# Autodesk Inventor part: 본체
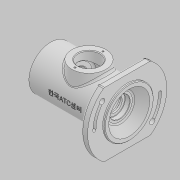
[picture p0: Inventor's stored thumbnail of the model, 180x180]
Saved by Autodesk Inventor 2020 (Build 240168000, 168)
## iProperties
Created: 2022-05
Part Number: 본체
Material: 일반
Document SubType Name: Modeling
Designer: User
Density: 1 g/cm^3
Appearance: 기본값
Author: User
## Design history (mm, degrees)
sketch "스케치1"
  geometry: L1 (0, 0)-(115, 0); L2 (115, 0)-(115, 36); L3 (115, 36)-(112, 36); L4 (112, 36)-(112, 58); L5 (112, 58)-(102, 58); L6 (102, 58)-(102, 32); L7 (102, 32)-(0, 32); L8 (0, 32)-(0, 0); L9 (11, 22.5)-(22, 22.5); L10 (22, 22.5)-(22, 17.5); L11 (22, 17.5)-(23.75, 17.5); L12 (23.75, 17.5)-(23.75, 18.5); L13 (23.75, 18.5)-(26, 18.5); L14 (26, 18.5)-(26, 17.5); L15 (26, 17.5)-(37, 17.5); L16 (37, 17.5)-(37, 27); L17 (75, 27)-(75, 17.5); L18 (75, 17.5)-(86, 17.5); L19 (86, 17.5)-(86, 15); L20 (86, 15)-(91, 15); L21 (91, 15)-(91, 11); L22 (91, 11)-(93.7, 11); L23 (93.7, 11)-(93.7, 15); L24 (101, 20)-(115, 30); L25 (93.7, 15)-(101, 15); L26 (101, 15)-(101, 20); L27 (37, 27)-(75, 27); L28 (11, 22.5)-(11, 24); L29 (11, 24)-(8, 24); L30 (8, 24)-(8, 22.5); L31 (8, 22.5)-(0, 22.5)
  constraints: 62 end point, 21 perpendicular, 4 horizontal, 2 point on line, 1 parallel, 1 vertical
  dimensions: "d0" = 115 distance of L1.start L1.end; "d1" = 72 diameter of L3 L1; "d2" = 116 diameter of L5 L1; "d3" = 64 diameter of L7 L1; "d4" = 13 distance between parallel lines of L6 L2; "d5" = 3 distance of L2.end L3.end; "d6" = 60 diameter of L24.end L1; "d7" = 40 diameter of L24.start L1; "d8" = 14 horizontal distance of L24.end L24.start; "d9" = 30 diameter of L25 L1; "d10" = 22 diameter of L22 L1; "d11" = 30 diameter of L20 L1; "d12" = 35 diameter of L18 L1; "d13" = 54 diameter of L27 L1; "d14" = 35 diameter of L15 L1; "d15" = 37 diameter of L13 L1; "d16" = 35 diameter of L11 L1; "d17" = 45 diameter of L9 L1; "d18" = 48 diameter of L29 L1; "d19" = 45 diameter of L31 L1; "d20" = 8 distance of L30.end L31.end; "d21" = 22 distance between parallel lines of L10 L8; "d22" = 3 distance of L28.end L29.end; "d23" = 29 distance between parallel lines of L19 L2; "d24" = 5 distance of L19.end L20.end; "d25" = 11 distance of L17.end L18.end; "d26" = 38 distance of L16.end L17.start; "d27" = 11 distance of L14.end L15.end; "d28" = 1.75 distance of L10.end L11.end; "d29" = 7.3 distance of L23.end L25.end
revolve "회전1" sketch "스케치1" stored, may be unused: angle "d30" = 90 deg
sketch "스케치2"
  geometry: L1 (-58, 47)-(58, 47); L2 (58, 47)-(58, -47); L3 (58, -47)-(-58, -47); L4 (-58, -47)-(-58, 47); A1 r 58 centre (0, 0) between (-58, 0) and (58, 0) reference; 5 further points
  constraints: 8 end point, 2 midpoint, 2 parallel, 2 point on circle, 1 horizontal, 1 horizontal alignment, 1 perpendicular
  dimensions: "d31" = 94 distance of L1.end L2.end
extrude "돌출1" cut sketch "스케치2" extent not by distance; stored distance "d32" = 0; taper "d33" = 0 deg
node "작업 평면1"
sketch "스케치3"
  geometry: C1 r 25 at (-56, 0); 1 further point
  constraints: 1 centre point, 1 horizontal alignment
  dimensions: "d35" = 50 diameter of C1; "d36" = 56 distance of C1.centre point (0, 0)
extrude "돌출2" join sketch "스케치3" stored distance "d37" = 10; taper "d38" = 5 deg
sketch "스케치4"
  geometry: C1 r 25 at (0, 0) reference; 2 further points
  constraints: 1 coincident
hole "구멍1" sketch "스케치4" at (0, 0) diameter "d39" = 32; stored, may be unused: countersink angle "d43" = 90 deg, drill point angle "d45" = 118 deg; dims "d40" = 6, "d41" = 4, "d42" = 2, "d44" = 8
sketch "스케치5"
  geometry: L1 (-48, 0)-(48, 0); L2 (-36.77, -30.854)-(36.77, 30.854); A1 r 48 centre (0, 0) between (48, 0) and (36.77, 30.854); A2 r 48 centre (0, 0) between (48, 0) and (36.77, 30.854); A3 r 52 centre (0, 0) between (52, 0) and (39.834, 33.425); A4 r 44 centre (0, 0) between (44, 0) and (33.706, 28.283); A5 r 4 centre (48, 0) between (44, 0) and (52, 0); A6 r 4 centre (36.77, 30.854) between (39.834, 33.425) and (33.706, 28.283); A7 r 50.25 centre (0, 0) between (50.25, 0) and (38.494, 32.3); A8 r 2.25 centre (48, 0) between (45.75, 0) and (50.25, 0); A9 r 45.75 centre (0, 0) between (45.75, 0) and (35.047, 29.408); A10 r 2.25 centre (36.77, 30.854) between (38.494, 32.3) and (35.047, 29.408); A11 r 48 centre (0, 0) between (-48, 0) and (-36.77, -30.854); A12 r 52 centre (0, 0) between (-52, 0) and (-39.834, -33.425); A13 r 44 centre (0, 0) between (-44, 0) and (-33.706, -28.283); A14 r 4 centre (-48, 0) between (-44, 0) and (-52, 0); A15 r 4 centre (-36.77, -30.854) between (-39.834, -33.425) and (-33.706, -28.283); A16 r 45.75 centre (0, 0) between (-45.75, 0) and (-35.047, -29.408); A17 r 2.25 centre (-48, 0) between (-45.75, 0) and (-50.25, 0); A18 r 50.25 centre (0, 0) between (-50.25, 0) and (-38.494, -32.3); A19 r 2.25 centre (-36.77, -30.854) between (-38.494, -32.3) and (-35.047, -29.408); 3 further points
  constraints: 40 point on circle, 19 centre point, 8 tangent, 5 coincident, 4 end point, 2 midpoint, 1 horizontal, 6 other
  dimensions: "d47" = 96 diameter of A1; "d48" = 40 deg angle of L2 L1; "d50" = 4 radius of A5; "d52" = 4.5 diameter of A8; "d53" = 4 radius of A15; "d54" = 4.5 diameter of A19
extrude "돌출3" cut sketch "스케치5" distance "d55" = 4.4; taper "d56" = 0 deg
extrude "돌출4" cut sketch "스케치5" extent not by distance; stored distance "d57" = 0; taper "d58" = 0 deg
hole "구멍2" sketch "스케치5" diameter "d59" = 8; stored, may be unused: countersink angle "d63" = 90 deg, drill point angle "d65" = 118 deg; dims "d60" = 6, "d61" = 4, "d62" = 2, "d64" = 8
sketch "스케치6" dims "d66" = 41
  geometry: L1 (0, 0)-(0, 20.5); C1 r 25 at (0, 0) reference; 2 further points
  constraints: 2 coincident, 2 end point, 1 vertical, 1 vertical alignment, 2 other
hole "구멍3" sketch "스케치6" at (0, 20.5) diameter "d67" = 2.62111; stored, may be unused: countersink angle "d71" = 90 deg, drill point angle "d73" = 118 deg; dims "d68" = 6, "d69" = 4, "d70" = 2, "d72" = 8
node "작업 평면2"
sketch "스케치7"
  geometry: L1 (64, -36)-(64, 36) reference; 2 further points
  constraints: 1 horizontal alignment, 1 other
  dimensions: "d77" = 62 distance from line of point (2, 0) L1
feature "엠보싱1" sketch "스케치7" dims "d78" = 0.5, "d79" = 0
chamfer "모따기1" distance "d80" = 0.7; stored, may be unused: second distance "d81" = 2, angle "d82" = 30 deg
chamfer "모따기2" distance "d83" = 1; stored, may be unused: second distance "d84" = 2, angle "d85" = 30 deg
fillet "모깎기1" dims "d86" = 0.5, "d87" = 0.6
fillet "모깎기2" dims "d88" = 3
feature "스레드1" dims "d89" = 8, "d90" = 0
fillet "모깎기3" dims "d91" = 3
chamfer "모따기3" distance "d92" = 1; stored, may be unused: second distance "d93" = 2, angle "d94" = 30 deg
fillet "모깎기4" dims "d95" = 3
node "솔리드1"
pattern_circular "원형 패턴1" dims angle "d75" = 360 deg
feature "A9D066F2-1C7D-4E18-AEED-F7BC21143FA4" dims "d89" = 8, "d90" = 0
other parameters: "d34" = 38
